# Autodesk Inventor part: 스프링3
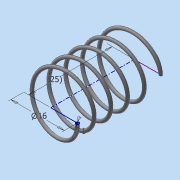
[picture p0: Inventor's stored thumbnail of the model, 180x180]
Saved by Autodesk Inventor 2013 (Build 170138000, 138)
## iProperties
Created: 2015-11
Part Number: 스프링3
Material: 일반
Document SubType Name: Modeling
Designer: dgall
Density: 1 g/cm^3
Author: dgall
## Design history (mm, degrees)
sketch "스케치1"
  geometry: L1 (8, 0)-(0, 0); L2 (0, 0)-(0, 25); L3 (0, 25)-(8, 25); C1 r 0.5 at (8, 0)
  constraints: 6 end point, 1 centre point, 1 coincident, 1 horizontal, 1 parallel, 1 perpendicular, 1 vertical alignment
  dimensions: "d5" = 16 diameter of L1.start L2; "d7" = 25 distance of L1.end L2.end (derived); "d8" = 1 diameter of C1
feature "코일1" pitch "d9" = 10; turns "d11" = 5; dims "d10" = 25 (= d7), "d12" = 0, angle "d13" = 90 deg, angle "d14" = 90 deg, "d15" = 0, "d16" = 0
sketch "스케치2"
  geometry: L1 (-10, 0)-(10, 0); L2 (10, 0)-(10, -5); L3 (10, -5)-(-10, -5); L4 (-10, -5)-(-10, 0); L5 (-10, 30)-(10, 30); L6 (10, 30)-(10, 25); L7 (10, 25)-(-10, 25); L8 (-10, 25)-(-10, 30); 4 further points
  constraints: 16 end point, 4 parallel, 3 midpoint, 2 horizontal, 2 perpendicular, 1 coincident, 1 vertical alignment
  dimensions: "d17" = 25 distance between parallel lines of L7 L1; "d18" = 5 distance of L7.end L5.start; "d19" = 5 distance of L3.end L1.start; "d20" = 20 distance of L2.end L3.end; "d21" = 20 distance of L5.start L5.end
extrude "돌출1" cut sketch "스케치2" stored distance "d22" = 30; taper "d23" = 0 deg
node "솔리드1"
